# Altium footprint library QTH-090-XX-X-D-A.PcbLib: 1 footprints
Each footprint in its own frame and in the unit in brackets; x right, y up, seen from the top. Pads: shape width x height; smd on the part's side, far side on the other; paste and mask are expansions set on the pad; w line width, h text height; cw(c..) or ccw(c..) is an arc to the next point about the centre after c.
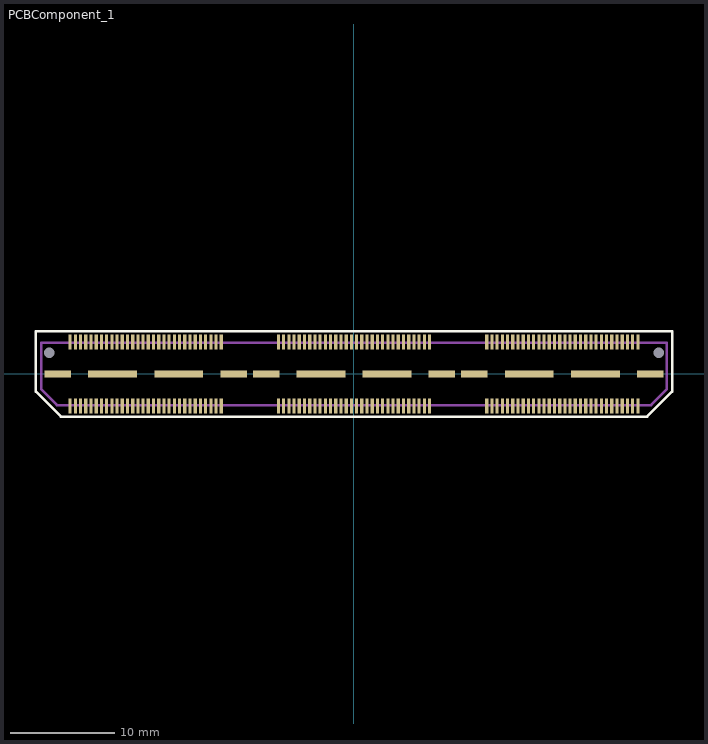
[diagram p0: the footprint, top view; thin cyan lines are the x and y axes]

## PCBComponent_1 [mil]
pads (194):
  rect 12x57 smd mask+2: 1(-1073.15,121.5) 2(-1073.15,-121.5) 3(-1053.45,121.5) 4(-1053.45,-121.5) 5(-1033.75,121.5) 6(-1033.75,-121.5) 7(-1014.05,121.5) 8(-1014.05,-121.5) 9(-994.35,121.5) 10(-994.35,-121.5) 11(-974.65,121.5) 12(-974.65,-121.5) 13(-954.95,121.5) 14(-954.95,-121.5) 15(-935.25,121.5) 16(-935.25,-121.5) 17(-915.55,121.5) 18(-915.55,-121.5) 19(-895.85,121.5) 20(-895.85,-121.5) 21(-876.15,121.5) 22(-876.15,-121.5) 23(-856.45,121.5) 24(-856.45,-121.5) 25(-836.75,121.5) 26(-836.75,-121.5) 27(-817.05,121.5) 28(-817.05,-121.5) 29(-797.35,121.5) 30(-797.35,-121.5) 31(-777.65,121.5) 32(-777.65,-121.5) 33(-757.95,121.5) 34(-757.95,-121.5) 35(-738.25,121.5) 36(-738.25,-121.5) 37(-718.55,121.5) 38(-718.55,-121.5) 39(-698.85,121.5) 40(-698.85,-121.5) 41(-679.15,121.5) 42(-679.15,-121.5) 43(-659.45,121.5) 44(-659.45,-121.5) 45(-639.75,121.5) 46(-639.75,-121.5) 47(-620.05,121.5) 48(-620.05,-121.5) 49(-600.35,121.5) 50(-600.35,-121.5) 51(-580.65,121.5) 52(-580.65,-121.5) 53(-560.95,121.5) 54(-560.95,-121.5) 55(-541.25,121.5) 56(-541.25,-121.5) 57(-521.55,121.5) 58(-521.55,-121.5) 59(-501.85,121.5) 60(-501.85,-121.5) 61(-285.65,121.5) 62(-285.65,-121.5) 63(-265.95,121.5) 64(-265.95,-121.5) 65(-246.25,121.5) 66(-246.25,-121.5) 67(-226.55,121.5) 68(-226.55,-121.5) 69(-206.85,121.5) 70(-206.85,-121.5) 71(-187.15,121.5) 72(-187.15,-121.5) 73(-167.45,121.5) 74(-167.45,-121.5) 75(-147.75,121.5) 76(-147.75,-121.5) 77(-128.05,121.5) 78(-128.05,-121.5) 79(-108.35,121.5) 80(-108.35,-121.5) 81(-88.65,121.5) 82(-88.65,-121.5) 83(-68.95,121.5) 84(-68.95,-121.5) 85(-49.25,121.5) 86(-49.25,-121.5) 87(-29.55,121.5) 88(-29.55,-121.5) 89(-9.85,121.5) 90(-9.85,-121.5) 91(9.85,121.5) 92(9.85,-121.5) 93(29.55,121.5) 94(29.55,-121.5) 95(49.25,121.5) 96(49.25,-121.5) 97(68.95,121.5) 98(68.95,-121.5) 99(88.65,121.5) 100(88.65,-121.5) 101(108.35,121.5) 102(108.35,-121.5) 103(128.05,121.5) 104(128.05,-121.5) 105(147.75,121.5) 106(147.75,-121.5) 107(167.45,121.5) 108(167.45,-121.5) 109(187.15,121.5) 110(187.15,-121.5) 111(206.85,121.5) 112(206.85,-121.5) 113(226.55,121.5) 114(226.55,-121.5) 115(246.25,121.5) 116(246.25,-121.5) 117(265.95,121.5) 118(265.95,-121.5) 119(285.65,121.5) 120(285.65,-121.5) 121(501.85,121.5) 122(501.85,-121.5) 123(521.55,121.5) 124(521.55,-121.5) 125(541.25,121.5) 126(541.25,-121.5) 127(560.95,121.5) 128(560.95,-121.5) 129(580.65,121.5) 130(580.65,-121.5) 131(600.35,121.5) 132(600.35,-121.5) 133(620.05,121.5) 134(620.05,-121.5) 135(639.75,121.5) 136(639.75,-121.5) 137(659.45,121.5) 138(659.45,-121.5) 139(679.15,121.5) 140(679.15,-121.5) 141(698.85,121.5) 142(698.85,-121.5) 143(718.55,121.5) 144(718.55,-121.5) 145(738.25,121.5) 146(738.25,-121.5) 147(757.95,121.5) 148(757.95,-121.5) 149(777.65,121.5) 150(777.65,-121.5) 151(797.35,121.5) 152(797.35,-121.5) 153(817.05,121.5) 154(817.05,-121.5) 155(836.75,121.5) 156(836.75,-121.5) 157(856.45,121.5) 158(856.45,-121.5) 159(876.15,121.5) 160(876.15,-121.5) 161(895.85,121.5) 162(895.85,-121.5) 163(915.55,121.5) 164(915.55,-121.5) 165(935.25,121.5) 166(935.25,-121.5) 167(954.95,121.5) 168(954.95,-121.5) 169(974.65,121.5) 170(974.65,-121.5) 171(994.35,121.5) 172(994.35,-121.5) 173(1014.05,121.5) 174(1014.05,-121.5) 175(1033.75,121.5) 176(1033.75,-121.5) 177(1053.45,121.5) 178(1053.45,-121.5) 179(1073.15,121.5) 180(1073.15,-121.5)
  rect 100x25 smd mask+2: 181(-1120,0) 184(-455,0) 185(-332.5,0) 188(332.5,0) 189(455,0) 192(1120,0)
  rect 185x25 smd mask+2: 182(-912.5,0) 183(-662.5,0) 186(-125,0) 187(125,0) 190(662.5,0) 191(912.5,0)
  round 0 hole 40 unplated: 193(-1151.5,80) 194(1151.5,80)
Top Overlay:
  lines w10: -1203,-67 -1108.58,-161.42 1108.58,-161.42 1203,-67 1203,161.42 -1203,161.42 -1203,-67
Mechanical 1:
  lines w10: -1183,-57.52 -1123,-117.52 1123,-117.52 1183,-57.52 1183,117.52 -1183,117.52 -1183,-57.52
  text "J1" at -17.56,-17.99 h30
